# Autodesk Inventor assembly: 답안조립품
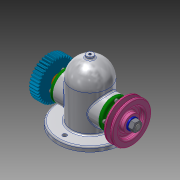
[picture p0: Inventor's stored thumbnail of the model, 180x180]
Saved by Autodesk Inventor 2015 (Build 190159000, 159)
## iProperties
Created: 2019-11
Part Number: 답안조립품
Document SubType Name: Assembly
Designer: Lineart
Author: Lineart
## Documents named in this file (14)
- C:\Users\Lineart\Desktop\491104V1013\답안조립품.iam
- C:\Users\Lineart\Desktop\491104V1013\본체.ipt
- C:\Users\Lineart\Desktop\491104V1013\491104V1013\베어링 6203.ipt
- C:\Users\Lineart\Desktop\491104V1013\491104V1013\축.ipt
- C:\Users\Lineart\Desktop\491104V1013\491104V1013\커버.ipt
- C:\Users\Lineart\Desktop\491104V1013\491104V1013\오일 실 26 38 8.ipt
- C:\Users\Lineart\Desktop\491104V1013\491104V1013\부시.ipt
- C:\Users\Lineart\Desktop\491104V1013\491104V1013\볼트 M4.ipt
- C:\Users\Lineart\Desktop\491104V1013\491104V1013\V-벨트풀리.ipt
- V-벨트풀리.ipt
- C:\Users\Lineart\Desktop\491104V1013\491104V1013\키 5x5x12.ipt
- C:\Users\Lineart\Desktop\491104V1013\491104V1013\와셔 12x24.ipt
- C:\Users\Lineart\Desktop\491104V1013\491104V1013\너트 M12x1.25.ipt
- C:\Users\Lineart\Desktop\491104V1013\491104V1013\스퍼기어.ipt
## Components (1 placed, 1 different names)
1. V-벨트풀리:1 — 각도:3
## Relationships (1: Angle 1)
- 각도:3 [Angle]: V-벨트풀리:1
